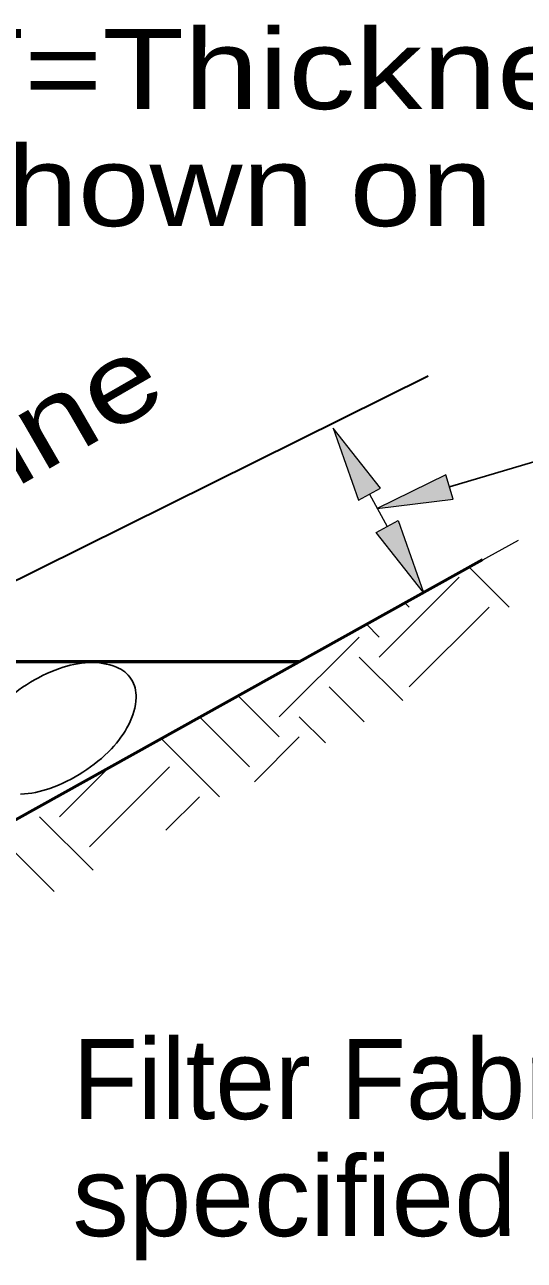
# Model space of a CAD drawing. Extents: x 72.6 to 107.3, y 36.1 to 58.1.
# Drawn here: x 89.68 to 90.509, y 37.902 to 39.953 of the extents above; entities that cross this region are included whole.
import ezdxf

# ---------------------------------------------------------------- set-up
doc = ezdxf.new("R2010")
doc.units = 0
doc.header["$LTSCALE"] = 0.053
for name, color, linetype, lineweight in [('1', 7, 'Continuous', 35), ('3', 7, 'Continuous', 13), ('4', 7, 'Continuous', 25), ('6', 7, 'Continuous', 13)]:
    doc.layers.add(name, color=color, linetype=linetype, lineweight=lineweight)

msp = doc.modelspace()

# ---------------------------------------------------------------- hatches: boundary and pattern name
at = {"layer": '3'}
for points in [[(90.23367, 39.16425), (90.27017, 39.18425), (90.19175, 39.28383), (90.19175, 39.28383)], [(90.23367, 39.16425), (90.27017, 39.18425), (90.19175, 39.28383), (90.19175, 39.28383)], [(90.39075, 39.166), (90.37892, 39.206), (90.265, 39.15042), (90.265, 39.15042)], [(90.39075, 39.166), (90.37892, 39.206), (90.265, 39.15042), (90.265, 39.15042)], [(90.26325, 39.11033), (90.29983, 39.13042), (90.34175, 39.01083), (90.34175, 39.01083)], [(90.26325, 39.11033), (90.29983, 39.13042), (90.34175, 39.01083), (90.34175, 39.01083)]]:
    msp.add_hatch(color=256, dxfattribs=at).paths.add_polyline_path(points)

# ---------------------------------------------------------------- linework, layer by layer
at = {"layer": '1', "lineweight": 25}
for p, q in [((90.26817, 38.90375), (90.40075, 39.03633)), ((90.26817, 38.90375), (90.40075, 39.03633)), ((90.26817, 38.90375), (90.40075, 39.03633)), ((90.48358, 38.98675), (90.41733, 39.053)), ((90.48358, 38.98675), (90.41733, 39.053)), ((90.48358, 38.98675), (90.41733, 39.053)), ((90.31792, 38.98667), (90.31092, 38.99367)), ((90.31792, 38.98667), (90.31092, 38.99367)), ((90.31792, 38.98667), (90.31092, 38.99367)), ((90.31792, 38.85408), (90.4505, 38.98667)), ((90.31792, 38.85408), (90.4505, 38.98667)), ((90.31792, 38.85408), (90.4505, 38.98667)), ((90.26817, 38.93692), (90.24708, 38.95808)), ((90.26817, 38.93692), (90.24708, 38.95808)), ((90.26817, 38.93692), (90.24708, 38.95808)), ((90.1025, 38.80433), (90.23508, 38.93692)), ((90.1025, 38.80433), (90.23508, 38.93692)), ((90.1025, 38.80433), (90.23508, 38.93692)), ((90.30725, 38.83158), (90.23508, 38.90375)), ((90.30725, 38.83158), (90.23508, 38.90375)), ((90.30725, 38.83158), (90.23508, 38.90375)), ((90.243, 38.79642), (90.18533, 38.85408)), ((90.243, 38.79642), (90.18533, 38.85408)), ((90.243, 38.79642), (90.18533, 38.85408)), ((90.1025, 38.77117), (90.03417, 38.8395)), ((90.1025, 38.77117), (90.03417, 38.8395)), ((90.1025, 38.77117), (90.03417, 38.8395)), ((90.05275, 38.7215), (89.97033, 38.80392)), ((90.05275, 38.7215), (89.97033, 38.80392)), ((90.05275, 38.7215), (89.97033, 38.80392)), ((90.17883, 38.76117), (90.13558, 38.80433)), ((90.17883, 38.76117), (90.13558, 38.80433)), ((90.17883, 38.76117), (90.13558, 38.80433)), ((90.00308, 38.67175), (89.9065, 38.76833)), ((90.00308, 38.67175), (89.9065, 38.76833)), ((90.00308, 38.67175), (89.9065, 38.76833)), ((90.00308, 38.67175), (89.9065, 38.76833)), ((90.00308, 38.67175), (89.9065, 38.76833)), ((90.00308, 38.67175), (89.9065, 38.76833)), ((90.06108, 38.69667), (90.13558, 38.77117)), ((90.06108, 38.69667), (90.13558, 38.77117)), ((90.06108, 38.69667), (90.13558, 38.77117)), ((89.73792, 38.63858), (89.81867, 38.71942)), ((89.73792, 38.63858), (89.81867, 38.71942)), ((89.73792, 38.63858), (89.81867, 38.71942)), ((89.78758, 38.58892), (89.92017, 38.7215)), ((89.78758, 38.58892), (89.92017, 38.7215)), ((89.78758, 38.58892), (89.92017, 38.7215)), ((89.73792, 38.67175), (89.73617, 38.6735)), ((89.73792, 38.67175), (89.73617, 38.6735)), ((89.73792, 38.67175), (89.73617, 38.6735)), ((89.91433, 38.61625), (89.96992, 38.67175)), ((89.91433, 38.61625), (89.96992, 38.67175)), ((89.91433, 38.61625), (89.96992, 38.67175)), ((89.79342, 38.54992), (89.70475, 38.63858)), ((89.79342, 38.54992), (89.70475, 38.63858)), ((89.79342, 38.54992), (89.70475, 38.63858)), ((89.72917, 38.51475), (89.655, 38.58892)), ((89.72917, 38.51475), (89.655, 38.58892)), ((89.72917, 38.51475), (89.655, 38.58892))]:
    msp.add_line(p, q, dxfattribs=at)
at = {"layer": '1', "lineweight": 53}
for points in [[(85.51933, 39.11467), (87.7205, 38.09742), (88.70217, 38.09742), (90.43975, 39.0655)], [(85.51933, 39.11467), (87.7205, 38.09742), (88.70217, 38.09742), (90.43975, 39.0655)], [(85.51933, 39.11467), (87.7205, 38.09742), (88.70217, 38.09742), (90.43975, 39.0655)], [(90.13483, 38.89558), (89.39158, 38.89558), (88.63417, 38.52808), (87.59975, 38.52808), (86.67942, 38.96392), (85.8455, 38.96392)], [(90.13483, 38.89558), (89.39158, 38.89558), (88.63417, 38.52808), (87.59975, 38.52808), (86.67942, 38.96392), (85.8455, 38.96392)]]:
    msp.add_lwpolyline(points, dxfattribs=at)
at = {"layer": '3', "lineweight": 35}
msp.add_line((89.60825, 39.003), (90.3495, 39.3705), dxfattribs=at)
msp.add_line((89.60825, 39.003), (90.3495, 39.3705), dxfattribs=at)
at = {"layer": '3'}
for p, q in [((90.25192, 39.17425), (90.2815, 39.12042)), ((90.25192, 39.17425), (90.2815, 39.12042)), ((90.39592, 39.04067), (90.4995, 39.09758)), ((90.39592, 39.04067), (90.4995, 39.09758))]:
    msp.add_line(p, q, dxfattribs=at)
at = {"layer": '3', "lineweight": 25}
msp.add_lwpolyline([(90.38483, 39.186), (91.98825, 39.6615), (91.14358, 39.6615)], dxfattribs=at)
msp.add_lwpolyline([(90.38483, 39.186), (91.98825, 39.6615), (91.14358, 39.6615)], dxfattribs=at)
at = {"layer": '3'}
for points in [[(90.23367, 39.16425), (90.27017, 39.18425), (90.19175, 39.28383), (90.19175, 39.28383)], [(90.23367, 39.16425), (90.27017, 39.18425), (90.19175, 39.28383), (90.19175, 39.28383)], [(90.39075, 39.166), (90.37892, 39.206), (90.265, 39.15042), (90.265, 39.15042)], [(90.39075, 39.166), (90.37892, 39.206), (90.265, 39.15042), (90.265, 39.15042)], [(90.26325, 39.11033), (90.29983, 39.13042), (90.34175, 39.01083), (90.34175, 39.01083)], [(90.26325, 39.11033), (90.29983, 39.13042), (90.34175, 39.01083), (90.34175, 39.01083)]]:
    msp.add_lwpolyline(points, close=True, dxfattribs=at)
at = {"layer": '4'}
for centre, radius, start, end in [((89.79558, 38.72125), 0.17343, 93.01003, 109.45885), ((89.79208, 38.78475), 0.10981, 68.6142, 92.93621), ((89.8255, 38.63683), 0.26298, 109.47631, 122.81482), ((89.81358, 38.83908), 0.05143, 32.92432, 68.81488), ((89.8255, 38.63708), 0.26276, 122.84584, 136.18434), ((89.81358, 38.83925), 0.05133, 356.85974, 32.7503), ((89.75492, 38.84225), 0.11007, 332.62903, 356.95103), ((89.699, 38.87125), 0.17306, 316.15944, 332.60826), ((89.63417, 38.93367), 0.26303, 302.79611, 316.13461), ((89.63417, 38.93325), 0.26266, 289.5108, 302.8493), ((89.66417, 38.84917), 0.17343, 273.01003, 289.45885)]:
    msp.add_arc(centre, radius, start, end, dxfattribs=at)
at = {"layer": '6'}
for p, q in [((90.19117, 39.2835), (90.19125, 39.2835)), ((90.19117, 39.2835), (90.19125, 39.2835)), ((90.34117, 39.0105), (90.34125, 39.0105)), ((90.34117, 39.0105), (90.34125, 39.0105)), ((90.34175, 39.01083), (90.34183, 39.01083)), ((90.34175, 39.01083), (90.34183, 39.01083))]:
    msp.add_line(p, q, dxfattribs=at)

# ---------------------------------------------------------------- texts
at = {"layer": '3'}
for s, width, p in [('T=Thickness of Dumped Rock', 1.25, (89.54308, 39.81333)), ('shown on plans', 1.2, (89.54308, 39.61908)), ('specified in plans', 1.05, (89.75933, 37.94242)), ('specified in plans', 1.05, (89.75933, 37.94242))]:
    msp.add_text(s, height=0.133, dxfattribs=dict(at, width=width)).set_placement(p)
at = {"layer": '3', "width": 1.25}
msp.add_text('Flow Line', height=0.133, rotation=29.938, dxfattribs=at).set_placement((89.09767, 38.85742))
at = {"layer": '3'}
msp.add_text('Filter Fabric if', height=0.133, dxfattribs=at).set_placement((89.75933, 38.13667))

doc.saveas('drawing.dxf')
